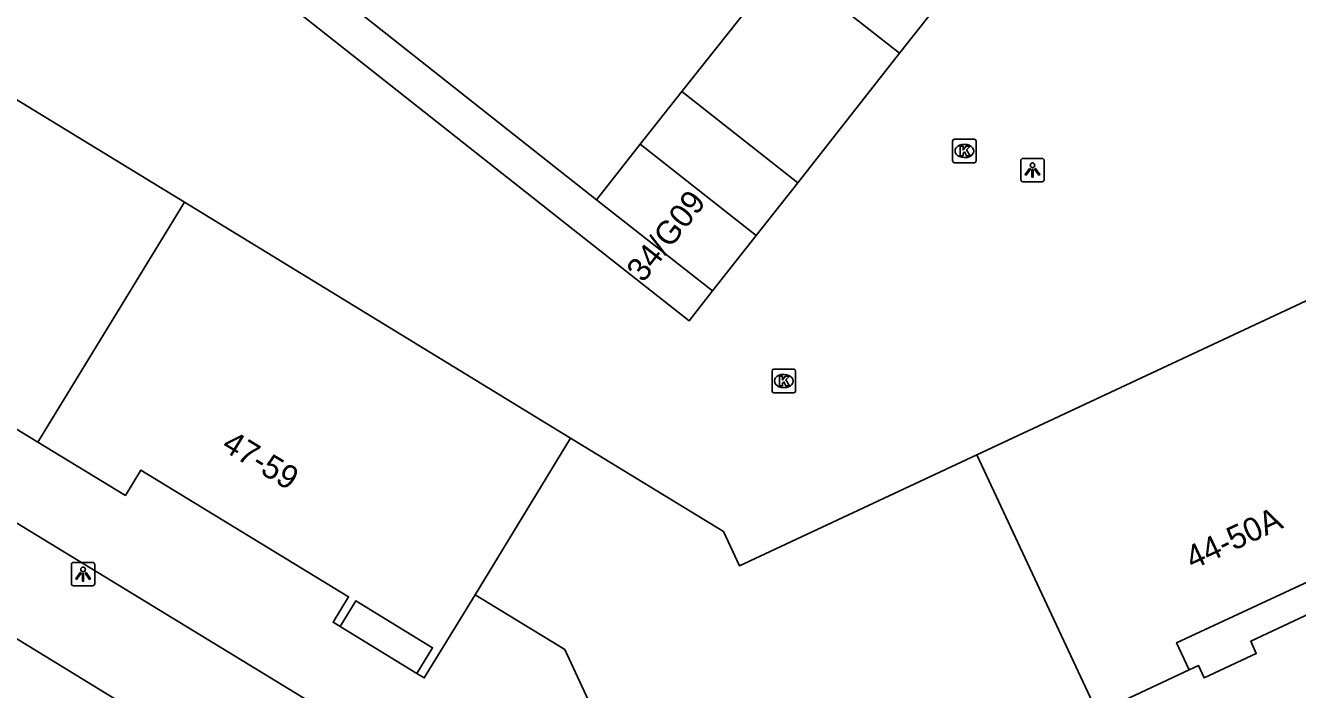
# Model space of a CAD drawing. Extents: x 158352 to 159489, y 383828 to 384597.
# Drawn here: x 158934.6 to 158988.7, y 383898.2 to 383926.5 of the extents above; entities that cross this region are included whole.
import ezdxf

# ---------------------------------------------------------------- set-up
doc = ezdxf.new("R2010")
doc.units = 0
for name, color, linetype in [('IMGEO_Kolk', 7, 'Continuous'), ('IMGEO_Lichtpunt', 7, 'Continuous'), ('IMGEO_Pand', 7, 'Continuous'), ('IMGEO_Pand_nummerreeks', 7, 'Continuous'), ('IMGEO_Pand_overbouw', 7, 'Continuous'), ('IMGEO_Voetpad_open', 7, 'Continuous')]:
    doc.layers.add(name, color=color, linetype=linetype)

msp = doc.modelspace()

# ---------------------------------------------------------------- linework, layer by layer
at = {"layer": 'IMGEO_Kolk'}
for p, q in [((158974.055, 383920.705), (158974.055, 383921.557)), ((158974.13, 383921.631), (158974.982, 383921.631)), ((158974.543, 383921.411), (158974.568, 383921.411)), ((158975.056, 383921.557), (158975.056, 383920.705)), ((158974.566, 383920.851), (158974.541, 383920.851)), ((158974.982, 383920.631), (158974.13, 383920.631)), ((158966.369, 383910.914), (158966.369, 383911.766)), ((158966.444, 383911.84), (158967.296, 383911.84)), ((158966.857, 383911.62), (158966.882, 383911.62)), ((158967.37, 383911.766), (158967.37, 383910.914)), ((158967.296, 383910.84), (158966.444, 383910.84)), ((158966.88, 383911.06), (158966.855, 383911.06))]:
    msp.add_line(p, q, dxfattribs=at)
for points in [[(158974.055, 383920.705), (158974.055, 383921.557)], [(158974.13, 383921.631), (158974.982, 383921.631)], [(158975.056, 383921.557), (158975.056, 383920.705)], [(158974.376, 383921.331), (158974.499, 383921.331), (158974.499, 383921.18), (158974.629, 383921.331), (158974.793, 383921.331), (158974.647, 383921.18), (158974.8, 383920.931), (158974.648, 383920.931), (158974.563, 383921.095), (158974.499, 383921.028), (158974.499, 383920.931), (158974.376, 383920.931), (158974.376, 383921.331)], [(158974.982, 383920.631), (158974.13, 383920.631)], [(158966.369, 383910.914), (158966.369, 383911.766)], [(158966.444, 383911.84), (158967.296, 383911.84)], [(158967.37, 383911.766), (158967.37, 383910.914)], [(158966.69, 383911.54), (158966.813, 383911.54), (158966.813, 383911.389), (158966.943, 383911.54), (158967.107, 383911.54), (158966.961, 383911.389), (158967.114, 383911.14), (158966.962, 383911.14), (158966.877, 383911.304), (158966.813, 383911.237), (158966.813, 383911.14), (158966.69, 383911.14), (158966.69, 383911.54)], [(158967.296, 383910.84), (158966.444, 383910.84)]]:
    msp.add_lwpolyline(points, dxfattribs=at)
for centre, start, end in [((158974.132, 383921.555), 91.552, 178.448), ((158974.132, 383921.555), 91.552, 178.448), ((158974.98, 383921.555), 1.552, 88.448), ((158974.98, 383921.555), 1.552, 88.448), ((158974.132, 383920.707), 181.552, 268.448), ((158974.132, 383920.707), 181.552, 268.448), ((158974.98, 383920.707), 271.552, 358.448), ((158974.98, 383920.707), 271.552, 358.448), ((158966.446, 383911.764), 91.552, 178.448), ((158966.446, 383911.764), 91.552, 178.448), ((158967.294, 383911.764), 1.552, 88.448), ((158967.294, 383911.764), 1.552, 88.448), ((158966.446, 383910.916), 181.552, 268.448), ((158966.446, 383910.916), 181.552, 268.448), ((158967.294, 383910.916), 271.552, 358.448), ((158967.294, 383910.916), 271.552, 358.448)]:
    msp.add_arc(centre, 0.0765, start, end, dxfattribs=at)
for centre, major_axis, ratio, start_param, end_param in [((158974.542, 383921.131), (-0.387, 0.002), 0.722429, 4.712389, 7.853982), ((158974.567, 383921.131), (-0.39, 0.002), 0.717154, 1.570796, 4.712389), ((158966.856, 383911.34), (-0.387, 0.002), 0.722429, 4.712389, 7.853982), ((158966.881, 383911.34), (-0.39, 0.002), 0.717154, 1.570796, 4.712389)]:
    msp.add_ellipse(centre, major_axis=major_axis, ratio=ratio, start_param=start_param, end_param=end_param, dxfattribs=at)
at = {"layer": 'IMGEO_Lichtpunt'}
for p, q in [((158977.855, 383920.818), (158977.047, 383920.818)), ((158977.855, 383920.818), (158977.047, 383920.818)), ((158976.953, 383920.723), (158976.953, 383919.916)), ((158976.953, 383920.723), (158976.953, 383919.916)), ((158977.949, 383919.916), (158977.949, 383920.723)), ((158977.949, 383919.916), (158977.949, 383920.723)), ((158977.047, 383919.822), (158977.855, 383919.822)), ((158977.047, 383919.822), (158977.855, 383919.822)), ((158936.554, 383903.524), (158936.554, 383902.717)), ((158936.554, 383903.524), (158936.554, 383902.717)), ((158937.456, 383903.619), (158936.648, 383903.619)), ((158937.456, 383903.619), (158936.648, 383903.619)), ((158937.55, 383902.717), (158937.55, 383903.524)), ((158937.55, 383902.717), (158937.55, 383903.524)), ((158936.648, 383902.623), (158937.456, 383902.623)), ((158936.648, 383902.623), (158937.456, 383902.623))]:
    msp.add_line(p, q, dxfattribs=at)
for points in [[(158977.327, 383920.387), (158977.366, 383920.359), (158977.178, 383920.097), (158977.14, 383920.124), (158977.327, 383920.387)], [(158977.429, 383920.339), (158977.476, 383920.339), (158977.476, 383920.017), (158977.429, 383920.017), (158977.429, 383920.339)], [(158977.539, 383920.359), (158977.577, 383920.386), (158977.764, 383920.124), (158977.725, 383920.096), (158977.539, 383920.359)], [(158936.928, 383903.188), (158936.967, 383903.16), (158936.779, 383902.898), (158936.741, 383902.925), (158936.928, 383903.188)], [(158937.03, 383903.14), (158937.077, 383903.14), (158937.077, 383902.818), (158937.03, 383902.818), (158937.03, 383903.14)], [(158937.14, 383903.16), (158937.178, 383903.187), (158937.365, 383902.925), (158937.326, 383902.897), (158937.14, 383903.16)]]:
    msp.add_lwpolyline(points, dxfattribs=at)
for centre in [(158977.452, 383920.521), (158937.053, 383903.322)]:
    msp.add_circle(centre, 0.0994, dxfattribs=at)
for centre, start, end in [((158977.047, 383920.723), 90, 180), ((158977.047, 383920.723), 90, 180), ((158977.855, 383920.723), 0, 90), ((158977.855, 383920.723), 0, 90), ((158977.047, 383919.916), 180, 270), ((158977.047, 383919.916), 180, 270), ((158977.855, 383919.916), 270, 0), ((158977.855, 383919.916), 270, 360), ((158936.648, 383903.524), 90, 180), ((158936.648, 383903.524), 90, 180), ((158937.456, 383903.524), 0, 90), ((158937.456, 383903.524), 0, 90), ((158936.648, 383902.717), 180, 270), ((158936.648, 383902.717), 180, 270), ((158937.456, 383902.717), 270, 0), ((158937.456, 383902.717), 270, 360)]:
    msp.add_arc(centre, 0.0946, start, end, dxfattribs=at)
at = {"layer": 'IMGEO_Pand'}
for points in [[(158935.131, 383908.739), (158931.408, 383911.01), (158932.07, 383912.095), (158923.17, 383917.524), (158922.528, 383916.47), (158922.2, 383916.67), (158922.843, 383917.725), (158919.543, 383919.738), (158918.859, 383918.617), (158918.515, 383918.827), (158924.769, 383929.082), (158929.037, 383926.476), (158941.365, 383918.947)], [(158962.534, 383923.657), (158966.89, 383929.155)], [(158966.89, 383929.155), (158971.799, 383925.296)], [(158973.579, 383927.56), (158971.799, 383925.296)], [(158971.799, 383925.296), (158967.465, 383919.782)], [(158960.759, 383921.417), (158962.534, 383923.657)], [(158962.534, 383923.657), (158967.465, 383919.782)], [(158960.759, 383921.417), (158958.903, 383919.055)], [(158965.698, 383917.535), (158960.759, 383921.417)], [(158967.465, 383919.782), (158965.698, 383917.535)], [(158941.365, 383918.947), (158935.131, 383908.739)], [(158941.365, 383918.947), (158957.8, 383908.909)], [(158958.903, 383919.055), (158963.842, 383915.174)], [(158963.842, 383915.174), (158965.698, 383917.535)], [(158975.086, 383908.195), (158992.369, 383916.279)], [(158957.8, 383908.909), (158953.73, 383902.244)], [(158957.8, 383908.909), (158964.3, 383904.939), (158964.984, 383903.469), (158975.086, 383908.195)], [(158953.73, 383902.244), (158951.571, 383898.705), (158951.261, 383898.894), (158951.928, 383899.988), (158948.659, 383901.982), (158947.992, 383900.889), (158947.69, 383901.073), (158948.353, 383902.159), (158939.513, 383907.551), (158938.853, 383906.469), (158935.131, 383908.739)], [(158980.221, 383897.216), (158975.086, 383908.195)], [(158984.12, 383899.047), (158983.586, 383900.199), (158993.014, 383904.583), (158993.536, 383903.464)], [(158962.629, 383888.952), (158957.549, 383899.914), (158953.73, 383902.244)], [(158984.12, 383899.047), (158980.221, 383897.216)]]:
    msp.add_lwpolyline(points, dxfattribs=at)
at = {"layer": 'IMGEO_Pand_overbouw'}
msp.add_lwpolyline([(158947.992, 383900.889), (158951.261, 383898.894), (158951.928, 383899.988), (158948.659, 383901.982)], close=True, dxfattribs=at)
at = {"layer": 'IMGEO_Voetpad_open'}
for points in [[(158932.342, 383940.038), (158957.085, 383920.484), (158958.903, 383919.055)], [(158931.11, 383938.956), (158957.903, 383917.789), (158962.844, 383913.905), (158962.945, 383914.033), (158963.842, 383915.174)], [(158915.787, 383916.891), (158916.804, 383915.918), (158953.058, 383893.805), (158954.443, 383892.578), (158956.068, 383888.808), (158957.202, 383886.391)], [(158919.951, 383899.296), (158924.33, 383906.424), (158939.279, 383897.273), (158934.676, 383889.98)], [(158993.536, 383903.464), (158993.112, 383903.254), (158993.342, 383902.726), (158991.125, 383901.695), (158990.884, 383902.21), (158986.743, 383900.268), (158986.973, 383899.738), (158984.751, 383898.703), (158984.522, 383899.225), (158984.12, 383899.047)]]:
    msp.add_lwpolyline(points, dxfattribs=at)

# ---------------------------------------------------------------- texts
at = {"layer": 'IMGEO_Pand_nummerreeks'}
for s, rotation, p in [('34/G09', 51.8298, (158960.887, 383915.493)), ('47-59', 328.6187, (158942.898, 383908.438)), ('44-50A', 24.9383, (158984.264, 383903.294))]:
    msp.add_text(s, height=1, rotation=rotation, dxfattribs=at).set_placement(p)

doc.saveas('drawing.dxf')
